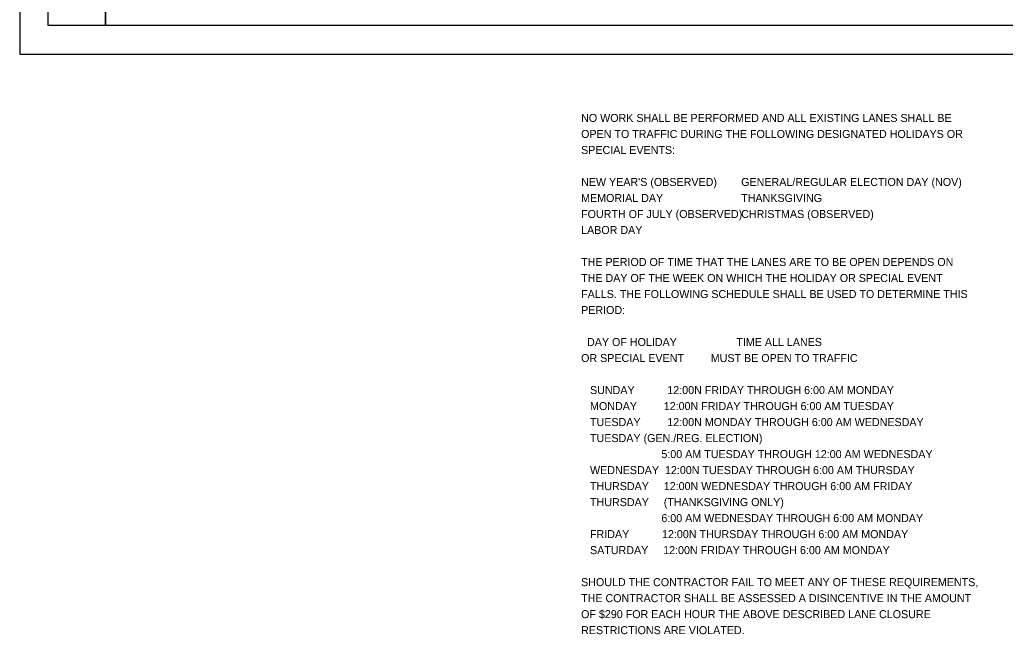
# Model space of a CAD drawing. Extents: x 0 to 34, y -10.1 to 22.
# Drawn here: x 0 to 17.24, y -10.15 to 0.6 of the extents above; entities that cross this region are included whole.
import ezdxf

# ---------------------------------------------------------------- set-up
doc = ezdxf.new("R2010")
doc.units = 0
for name, color, linetype in [('SH_Border', 7, 'Continuous'), ('SH_Cut_Line', 7, 'Continuous'), ('SH_Data', 7, 'Continuous'), ('SH_Text', 7, 'Continuous')]:
    doc.layers.add(name, color=color, linetype=linetype)

msp = doc.modelspace()

# ---------------------------------------------------------------- linework, layer by layer
at = {"layer": 'SH_Border'}
for points in [[(0.5, 21.5), (1.5, 21.5), (1.5, 0.5), (0.5, 0.5)], [(1.5, 21.5), (33.5, 21.5), (33.5, 0.5), (1.5, 0.5)]]:
    msp.add_lwpolyline(points, close=True, dxfattribs=at)
at = {"layer": 'SH_Cut_Line'}
msp.add_lwpolyline([(0, 0), (34, 0), (34, 22), (0, 22)], close=True, dxfattribs=at)
at = {"layer": 'SH_Data'}
for p, q in [((0.6, 0.6), (0.6, 0.6)), ((0, 0), (0, 0))]:
    msp.add_line(p, q, dxfattribs=at)

# ---------------------------------------------------------------- texts
at = {"layer": 'SH_Text'}
for s, p in [('NO WORK SHALL BE PERFORMED AND ALL EXISTING LANES SHALL BE ', (9.82, -1.185)), ('OPEN TO TRAFFIC DURING THE FOLLOWING DESIGNATED HOLIDAYS OR ', (9.82, -1.465)), ('SPECIAL EVENTS:', (9.82, -1.745)), ("NEW YEAR'S (OBSERVED)", (9.82, -2.305)), ('GENERAL/REGULAR ELECTION DAY (NOV) ', (12.62, -2.305)), ('MEMORIAL DAY', (9.82, -2.585)), ('THANKSGIVING', (12.62, -2.585)), ('FOURTH OF JULY (OBSERVED)', (9.82, -2.865)), ('CHRISTMAS (OBSERVED)', (12.62, -2.865)), ('LABOR DAY', (9.82, -3.145)), ('THE PERIOD OF TIME THAT THE LANES ARE TO BE OPEN DEPENDS ON ', (9.82, -3.705)), ('THE DAY OF THE WEEK ON WHICH THE HOLIDAY OR SPECIAL EVENT ', (9.82, -3.985)), ('FALLS. THE FOLLOWING SCHEDULE SHALL BE USED TO DETERMINE THIS ', (9.82, -4.265)), ('PERIOD:', (9.82, -4.545)), ('  DAY OF HOLIDAY                    TIME ALL LANES', (9.82, -5.105)), ('OR SPECIAL EVENT         MUST BE OPEN TO TRAFFIC', (9.82, -5.385)), ('   SUNDAY           12:00N FRIDAY THROUGH 6:00 AM MONDAY', (9.82, -5.945)), ('   MONDAY         12:00N FRIDAY THROUGH 6:00 AM TUESDAY', (9.82, -6.225)), ('   TUESDAY         12:00N MONDAY THROUGH 6:00 AM WEDNESDAY', (9.82, -6.505)), ('   TUESDAY (GEN./REG. ELECTION)', (9.82, -6.785)), ('                           5:00 AM TUESDAY THROUGH 12:00 AM WEDNESDAY', (9.82, -7.065)), ('   WEDNESDAY  12:00N TUESDAY THROUGH 6:00 AM THURSDAY', (9.82, -7.345)), ('   THURSDAY     12:00N WEDNESDAY THROUGH 6:00 AM FRIDAY', (9.82, -7.625)), ('   THURSDAY     (THANKSGIVING ONLY)', (9.82, -7.905)), ('                           6:00 AM WEDNESDAY THROUGH 6:00 AM MONDAY', (9.82, -8.185)), ('   FRIDAY           12:00N THURSDAY THROUGH 6:00 AM MONDAY', (9.82, -8.465)), ('   SATURDAY     12:00N FRIDAY THROUGH 6:00 AM MONDAY', (9.82, -8.745)), ('SHOULD THE CONTRACTOR FAIL TO MEET ANY OF THESE REQUIREMENTS, ', (9.82, -9.305)), ('THE CONTRACTOR SHALL BE ASSESSED A DISINCENTIVE IN THE AMOUNT ', (9.82, -9.585)), ('OF $290 FOR EACH HOUR THE ABOVE DESCRIBED LANE CLOSURE ', (9.82, -9.865)), ('RESTRICTIONS ARE VIOLATED.', (9.82, -10.145))]:
    msp.add_text(s, height=0.14, dxfattribs=at).set_placement(p)

doc.saveas('drawing.dxf')
